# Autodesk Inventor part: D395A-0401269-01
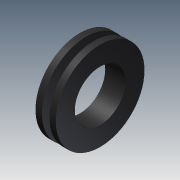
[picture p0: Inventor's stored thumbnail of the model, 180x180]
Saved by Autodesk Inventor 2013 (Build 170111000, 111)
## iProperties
Created: 2002-06
Part Number: D395A-0401269-01
Material: Rubber
Document SubType Name: Modeling
Designer: PVitaliy
Density: 0.93 g/cm^3
Mass: 3.61777 g
Surface Area: 34.5575 cm^2
Volume: 3.89008 cm^3
Author: PVitaliy
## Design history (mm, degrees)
derived "D395A-0401269.ipt"
body "Solid1"
tag "TaggingFeature2"
feature "DerivedBody::D395A-0401269.ipt" dims "d0" = 10
